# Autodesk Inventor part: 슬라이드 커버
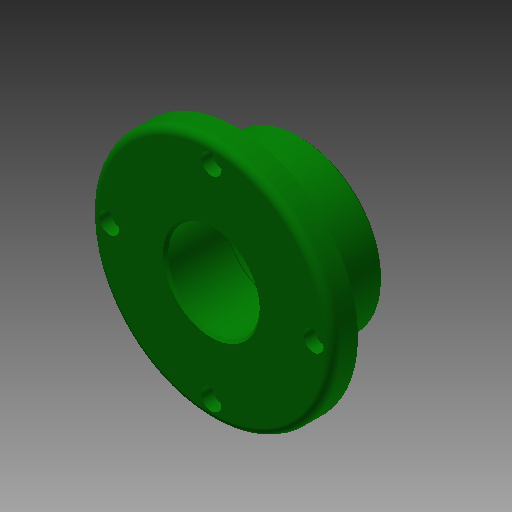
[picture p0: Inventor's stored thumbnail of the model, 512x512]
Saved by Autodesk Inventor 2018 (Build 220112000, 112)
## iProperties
Created: 2015-10
Part Number: 슬라이드 커버
Document SubType Name: Modeling
Designer: mdu
Density: 7.86 g/cm^3
Material: 강철, 연강
Mass: 598.523 g
Surface Area: 229.996 cm^2
Volume: 76.148 cm^3
Appearance: 진녹색
Author: mdu
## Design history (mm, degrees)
sketch "스케치1"
  geometry: C1 r 47.5 at (0, 0); C2 r 32.5 at (0, 0); 1 further point
  constraints: 2 centre point, 2 coincident
  dimensions: "d33" = 95 diameter of C1; "d35" = 65 diameter of C2
extrude "돌출1" new body sketch "스케치1" distance "d0" = 10; taper "d1" = 0 deg
extrude "돌출2" join sketch "스케치1" distance "d2" = 25; taper "d3" = 0 deg
hole "구멍1" diameter "d6" = 36; stored, may be unused: countersink angle "d10" = 90 deg, drill point angle "d12" = 118 deg; dims "d7" = 6, "d8" = 4, "d9" = 2, "d11" = 8, "d41" = 10, "d42" = 10
sketch "스케치2" dims "d36" = 80
  geometry: 4 further points
  constraints: 2 coincident, 2 vertical alignment, 2 other
hole "구멍2" sketch "스케치2" at (0, 40) diameter "d13" = 4.5; stored, may be unused: countersink angle "d17" = 90 deg, drill point angle "d19" = 118 deg; dims "d14" = 6, "d15" = 8, "d16" = 4.4, "d18" = 8
fillet "모깎기1" dims "d23" = 3
chamfer "모따기1" distance "d24" = 1; stored, may be unused: second distance "d25" = 2, angle "d26" = 45 deg
sketch "스케치3"
  geometry: C1 r 26 at (0, 0); C2 r 19 at (0, 0) reference; 1 further point
  constraints: 1 centre point, 1 concentric
  dimensions: "d27" = 52 diameter of C1
extrude "돌출3" cut sketch "스케치3" distance "d28" = 10; taper "d29" = 0 deg
chamfer "모따기2" distance "d30" = 1; stored, may be unused: second distance "d31" = 2, angle "d32" = 45 deg
node "솔리드1"
pattern_circular "원형 패턴1" dims angle "d21" = 360 deg
